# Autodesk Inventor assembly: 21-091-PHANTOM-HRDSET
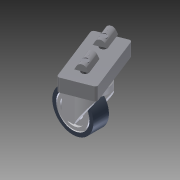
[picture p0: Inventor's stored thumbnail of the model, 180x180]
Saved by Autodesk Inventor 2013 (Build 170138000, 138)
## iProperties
Created: 2004-11
Part Number: 21-091-PHANTOM-HRDSET
Document SubType Name: Assembly
Designer: Autodesk, Inc.
Manufacturer: Standard
Standards Organization: Custom
Description: PHANTOM, CASTER, HARDWARE SET
Catalog Web Link: http://www.parker.com/ead/cm1.asp?cmid=809
Vendor: PARKER IPS
Mass: 438.65 g
Surface Area: 350.869 cm^2
Volume: 101.466 cm^3
Density: 4.32314 g/cm^3
CAGE: 1LJX3
Dept. ID: Product Design
Description #2: ---
Finish #1: ---
Finish #2: ---
Material ID: ---
Project Number: ---
Author: Autodesk, Inc.
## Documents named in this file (4)
- Z:\_DATEN\Test Station\Components\21-091 Caster Phantom.iam
- Z:\_DATEN\Test Station\Components\21-091 Caster.ipt
- Z:\_DATEN\Test Station\Components\21-09x_Caster_Mnt_Phantom.iam
- Z:\_DATEN\Test Station\Components\M10x25-Spring Phantom.iam
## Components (3 placed, 3 different names)
1. 21-091 Caster:1
2. 21-09x_Caster_Mnt_Phantom:1 [sub-assembly]
3. M10x25-Spring Phantom:1 [sub-assembly]
